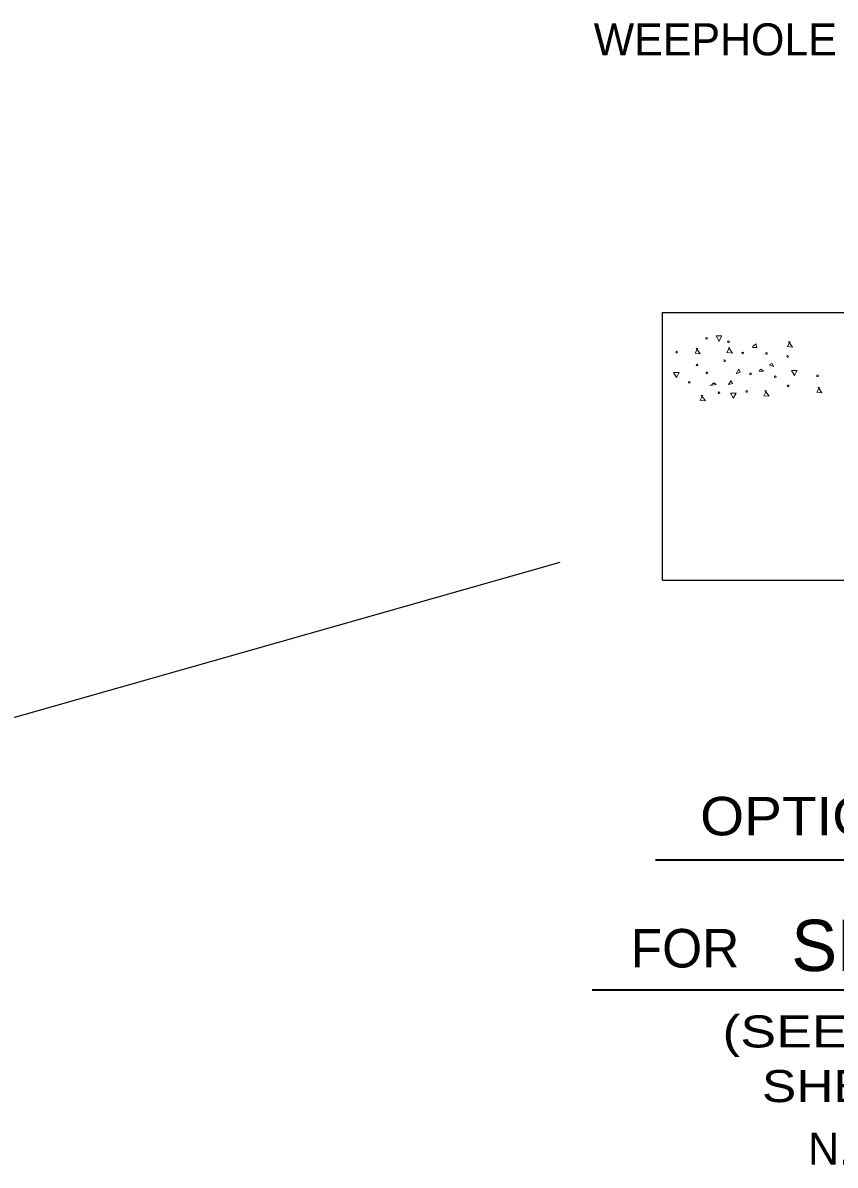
# Model space of a CAD drawing. Extents: x -28.1 to 13.9, y -16.1 to 13.9.
# Drawn here: x -0.567 to 2.598, y -6.999 to -2.545 of the extents above; entities that cross this region are included whole.
import ezdxf
from ezdxf.enums import TextEntityAlignment as Align

# ---------------------------------------------------------------- set-up
doc = ezdxf.new("R2010")
doc.units = 0
doc.header["$LTSCALE"] = 0.05
doc.layers.add('1', color=7, linetype='Continuous', lineweight=13)
doc.layers.add('2', color=7, linetype='Continuous', lineweight=13)

msp = doc.modelspace()

# ---------------------------------------------------------------- linework, layer by layer
at = {"layer": '1', "lineweight": 25}
for p, q in [((1.92496, -3.67531), (3.15196, -3.67531)), ((1.92496, -4.71831), (1.92496, -3.67531)), ((1.92496, -4.71831), (3.15196, -4.71831))]:
    msp.add_line(p, q, dxfattribs=at)
at = {"layer": '1', "lineweight": 35}
for p, q in [((1.89796, -5.80831), (5.29896, -5.80831)), ((1.65096, -6.31531), (5.39896, -6.31531))]:
    msp.add_line(p, q, dxfattribs=at)
at = {"layer": '1', "lineweight": 25}
msp.add_lwpolyline([(1.52496, -4.64931), (-2.40604, -5.76731), (-2.14604, -5.62931)], dxfattribs=at)
at = {"layer": '2'}
msp.add_line((2.27596, -3.80731), (2.28796, -3.79731), dxfattribs=at)
for points in [[(2.14396, -3.78331), (2.13396, -3.76531), (2.15596, -3.76531), (2.14396, -3.78731)], [(2.06196, -3.81331), (2.05196, -3.83331), (2.07196, -3.83531), (2.05596, -3.81331)], [(2.18596, -3.81131), (2.17596, -3.83131), (2.19796, -3.83331), (2.18196, -3.81131)], [(2.28796, -3.79731), (2.29196, -3.81131), (2.27596, -3.81131)], [(2.42196, -3.78731), (2.41196, -3.80731), (2.43196, -3.80931), (2.41596, -3.78731)], [(2.34196, -3.87731), (2.35196, -3.87331), (2.35796, -3.88531), (2.34196, -3.87931)], [(1.97796, -3.92531), (1.96796, -3.90931), (1.98996, -3.90931), (1.97796, -3.92931)], [(2.30196, -3.90331), (2.30796, -3.89531), (2.31796, -3.90331), (2.30396, -3.90531)], [(2.43796, -3.91731), (2.42796, -3.90131), (2.44996, -3.90131), (2.43796, -3.92131)], [(2.11596, -3.95531), (2.12596, -3.94931), (2.13396, -3.95531), (2.10996, -3.95931)], [(2.08196, -3.99731), (2.07196, -4.01731), (2.09196, -4.01931), (2.07596, -3.99731)], [(2.19996, -4.00731), (2.18996, -3.98931), (2.21196, -3.98931), (2.19996, -4.00931)], [(2.32996, -3.97931), (2.31996, -3.99931), (2.33996, -4.00131), (2.32396, -3.97931)], [(2.53596, -3.96531), (2.52596, -3.98531), (2.54596, -3.98731), (2.53196, -3.96531)]]:
    msp.add_lwpolyline(points, dxfattribs=at)
for points in [[(2.21196, -3.91331), (2.22196, -3.89531), (2.22796, -3.90731)], [(2.18196, -3.95531), (2.19196, -3.93931), (2.19796, -3.95131)]]:
    msp.add_lwpolyline(points, close=True, dxfattribs=at)
for centre in [(2.09646, -3.77556), (1.97996, -3.82906), (2.18196, -3.78906), (2.23746, -3.83256), (2.16696, -3.86306), (2.32996, -3.83456), (2.41246, -3.84606), (2.05946, -3.87956), (2.09796, -3.91006), (2.26796, -3.91356), (2.52896, -3.92156), (2.02896, -3.94706), (2.36396, -3.92506), (2.41446, -3.96056), (2.14496, -3.98756), (2.25296, -3.98256)]:
    msp.add_circle(centre, 0.00325, dxfattribs=at)

# ---------------------------------------------------------------- texts
at = {"layer": '1'}
for s, height, p in [('WEEPHOLE', 0.125, (2.60427, -2.67231)), ('FOR', 0.15, (2.22443, -6.22831))]:
    msp.add_text(s, height=height, dxfattribs=at).set_placement(p, align=Align.RIGHT)
for s, height, width, p in [('OPTIONAL DRAINAGE DETAIL', 0.15, 1.1, (3.65313, -5.71331)), ('(SEE NOTE 5,', 0.125, 1.25, (2.8378, -6.54031)), ('SHEET 2)', 0.125, 1.2, (2.76377, -6.75331))]:
    msp.add_text(s, height=height, dxfattribs=dict(at, width=width)).set_placement(p, align=Align.CENTER)
for s, height, p in [('SECTION', 0.2, (3.02136, -6.24231)), ('N.T.S.', 0.125, (2.72882, -6.99731))]:
    msp.add_text(s, height=height, dxfattribs=at).set_placement(p, align=Align.CENTER)

doc.saveas('drawing.dxf')
